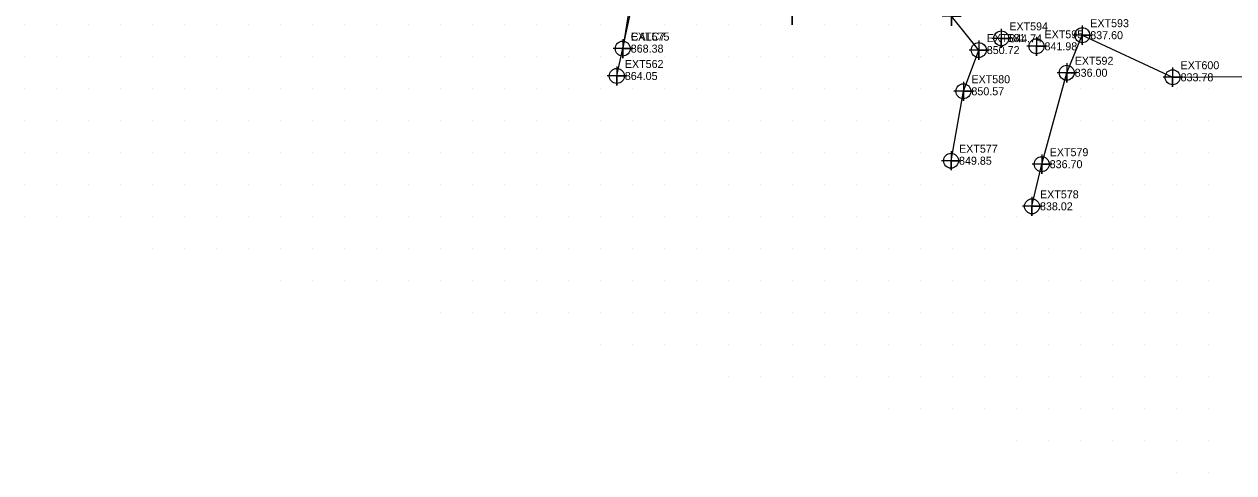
# Model space of a CAD drawing. Extents: x 1762120 to 1766775, y 709485 to 712965.
# Drawn here: x 1762430 to 1762807.8, y 712460 to 712600.2 of the extents above; entities that cross this region are included whole.
import ezdxf

# ---------------------------------------------------------------- set-up
doc = ezdxf.new("R2010")
doc.units = 0
for name, color, linetype in [('Exist Building', 7, 'Continuous'), ('Exist Building Cogo Elevation', 7, 'Continuous'), ('Exist Building Cogo Number', 7, 'Continuous'), ('Exist Building Cogo Point CELL', 7, 'Continuous'), ('Exist DTM Breakline', 7, 'Continuous'), ('Exist DTM Breakline Cogo Elevation', 7, 'Continuous'), ('Exist DTM Breakline Cogo Number', 7, 'Continuous'), ('Exist DTM Breakline Cogo Point CELL', 7, 'Continuous'), ('Exist DTM Drainline Cogo Elevation', 7, 'Continuous'), ('Exist DTM Drainline Cogo Number', 7, 'Continuous'), ('Exist DTM Drainline Cogo Point CELL', 7, 'Continuous'), ('Exist DTM QL2 LIDAR Elevation Point', 7, 'Continuous'), ('Exist DTM Regular Point CELL', 7, 'Continuous')]:
    doc.layers.add(name, color=color, linetype=linetype)

msp = doc.modelspace()

# ---------------------------------------------------------------- linework, layer by layer
at = {"layer": 'Exist Building'}
msp.add_lwpolyline([(1762599.52, 712660.55), (1762603.8, 712657.24), (1762612.48, 712646.81), (1762616.85, 712638.07), (1762621.8, 712624.37), (1762620.27, 712613.6), (1762616.96, 712592.54)], dxfattribs=at)
at = {"layer": 'Exist Building Cogo Point CELL'}
msp.add_lwpolyline([(1762616.96, 712595.54), (1762616.96, 712589.54), (1762616.96, 712592.54), (1762619.96, 712592.54), (1762613.96, 712592.54)], dxfattribs=at)
msp.add_circle((1762616.96, 712592.54), 2.34, dxfattribs=at)
at = {"layer": 'Exist DTM Breakline'}
for points in [[(1762615.11, 712583.99), (1762620.08, 712607.1), (1762622.12, 712625.39), (1762617.91, 712637.23), (1762609.81, 712651.19), (1762604.91, 712656.95), (1762600.21, 712661.1)], [(1762599.52, 712660.55), (1762603.8, 712657.24), (1762612.39, 712646.67), (1762616.85, 712638.07), (1762621.8, 712624.37), (1762620.27, 712613.6), (1762616.98, 712592.72)], [(1762719.5, 712557.51), (1762723.37, 712579.21), (1762728.17, 712592.08), (1762719.69, 712602.68), (1762720.68, 712608.52), (1762728.46, 712607.7), (1762735.49, 712603.43), (1762739.91, 712614.08), (1762743.86, 712621.24), (1762758.62, 712619.92), (1762767.95, 712615.27), (1762785.33, 712612.97), (1762818.77, 712608.04), (1762844.34, 712603.2), (1762875.47, 712595.47), (1762904.98, 712592.7), (1762941.56, 712585.95), (1762969.55, 712578.67)], [(1762744.79, 712543.26), (1762747.82, 712556.43), (1762755.63, 712584.99), (1762760.49, 712596.73), (1762788.71, 712583.59), (1762810.99, 712583.79), (1762841.1, 712578.61), (1762868.62, 712575.07), (1762897.75, 712577.65), (1762898.22, 712561.48), (1762885.56, 712560.4), (1762873.7, 712557.52), (1762863.74, 712551.2)]]:
    msp.add_lwpolyline(points, dxfattribs=at)
at = {"layer": 'Exist DTM Breakline Cogo Point CELL'}
for points in [[(1762719.69, 712605.68), (1762719.69, 712599.68), (1762719.69, 712602.68), (1762722.69, 712602.68), (1762716.69, 712602.68)], [(1762760.49, 712599.73), (1762760.49, 712593.73), (1762760.49, 712596.73), (1762763.49, 712596.73), (1762757.49, 712596.73)], [(1762616.96, 712595.54), (1762616.96, 712589.54), (1762616.96, 712592.54), (1762619.96, 712592.54), (1762613.96, 712592.54)], [(1762728.17, 712595.08), (1762728.17, 712589.08), (1762728.17, 712592.08), (1762731.17, 712592.08), (1762725.17, 712592.08)], [(1762615.11, 712586.99), (1762615.11, 712580.99), (1762615.11, 712583.99), (1762618.11, 712583.99), (1762612.11, 712583.99)], [(1762755.63, 712587.99), (1762755.63, 712581.99), (1762755.63, 712584.99), (1762758.63, 712584.99), (1762752.63, 712584.99)], [(1762788.71, 712586.59), (1762788.71, 712580.59), (1762788.71, 712583.59), (1762791.71, 712583.59), (1762785.71, 712583.59)], [(1762723.37, 712582.21), (1762723.37, 712576.21), (1762723.37, 712579.21), (1762726.37, 712579.21), (1762720.37, 712579.21)], [(1762719.5, 712560.51), (1762719.5, 712554.51), (1762719.5, 712557.51), (1762722.5, 712557.51), (1762716.5, 712557.51)], [(1762747.82, 712559.43), (1762747.82, 712553.43), (1762747.82, 712556.43), (1762750.82, 712556.43), (1762744.82, 712556.43)], [(1762744.79, 712546.26), (1762744.79, 712540.26), (1762744.79, 712543.26), (1762747.79, 712543.26), (1762741.79, 712543.26)]]:
    msp.add_lwpolyline(points, dxfattribs=at)
for centre in [(1762760.49, 712596.73), (1762616.96, 712592.54), (1762728.17, 712592.08), (1762615.11, 712583.99), (1762755.63, 712584.99), (1762788.71, 712583.59), (1762723.37, 712579.21), (1762719.5, 712557.51), (1762747.82, 712556.43), (1762744.79, 712543.26)]:
    msp.add_circle(centre, 2.34, dxfattribs=at)
at = {"layer": 'Exist DTM Drainline Cogo Point CELL'}
for points in [[(1762735.2, 712598.74), (1762735.2, 712592.74), (1762735.2, 712595.74), (1762738.2, 712595.74), (1762732.2, 712595.74)], [(1762746.2, 712596.26), (1762746.2, 712590.26), (1762746.2, 712593.26), (1762749.2, 712593.26), (1762743.2, 712593.26)]]:
    msp.add_lwpolyline(points, dxfattribs=at)
for centre in [(1762735.2, 712595.74), (1762746.2, 712593.26)]:
    msp.add_circle(centre, 2.34, dxfattribs=at)
at = {"layer": 'Exist DTM QL2 LIDAR Elevation Point'}
for p, q in [((1762430, 712600), (1762430, 712600)), ((1762440, 712600), (1762440, 712600)), ((1762450, 712600), (1762450, 712600)), ((1762460, 712600), (1762460, 712600)), ((1762470, 712600), (1762470, 712600)), ((1762480, 712600), (1762480, 712600)), ((1762490, 712600), (1762490, 712600)), ((1762500, 712600), (1762500, 712600)), ((1762510, 712600), (1762510, 712600)), ((1762520, 712600), (1762520, 712600)), ((1762530, 712600), (1762530, 712600)), ((1762540, 712600), (1762540, 712600)), ((1762550, 712600), (1762550, 712600)), ((1762560, 712600), (1762560, 712600)), ((1762570, 712600), (1762570, 712600)), ((1762580, 712600), (1762580, 712600)), ((1762590, 712600), (1762590, 712600)), ((1762600, 712600), (1762600, 712600)), ((1762610, 712600), (1762610, 712600)), ((1762630, 712600), (1762630, 712600)), ((1762640, 712600), (1762640, 712600)), ((1762650, 712600), (1762650, 712600)), ((1762660, 712600), (1762660, 712600)), ((1762670, 712600), (1762670, 712600)), ((1762680, 712600), (1762680, 712600)), ((1762690, 712600), (1762690, 712600)), ((1762700, 712600), (1762700, 712600)), ((1762710, 712600), (1762710, 712600)), ((1762430, 712590), (1762430, 712590)), ((1762440, 712590), (1762440, 712590)), ((1762450, 712590), (1762450, 712590)), ((1762460, 712590), (1762460, 712590)), ((1762470, 712590), (1762470, 712590)), ((1762480, 712590), (1762480, 712590)), ((1762490, 712590), (1762490, 712590)), ((1762500, 712590), (1762500, 712590)), ((1762510, 712590), (1762510, 712590)), ((1762520, 712590), (1762520, 712590)), ((1762530, 712590), (1762530, 712590)), ((1762540, 712590), (1762540, 712590)), ((1762550, 712590), (1762550, 712590)), ((1762560, 712590), (1762560, 712590)), ((1762570, 712590), (1762570, 712590)), ((1762580, 712590), (1762580, 712590)), ((1762590, 712590), (1762590, 712590)), ((1762600, 712590), (1762600, 712590)), ((1762610, 712590), (1762610, 712590)), ((1762620, 712590), (1762620, 712590)), ((1762630, 712590), (1762630, 712590)), ((1762640, 712590), (1762640, 712590)), ((1762650, 712590), (1762650, 712590)), ((1762660, 712590), (1762660, 712590)), ((1762670, 712590), (1762670, 712590)), ((1762680, 712590), (1762680, 712590)), ((1762690, 712590), (1762690, 712590)), ((1762700, 712590), (1762700, 712590)), ((1762710, 712590), (1762710, 712590)), ((1762720, 712590), (1762720, 712590)), ((1762760, 712590), (1762760, 712590)), ((1762770, 712590), (1762770, 712590)), ((1762430, 712580), (1762430, 712580)), ((1762440, 712580), (1762440, 712580)), ((1762450, 712580), (1762450, 712580)), ((1762460, 712580), (1762460, 712580)), ((1762470, 712580), (1762470, 712580)), ((1762480, 712580), (1762480, 712580)), ((1762490, 712580), (1762490, 712580)), ((1762500, 712580), (1762500, 712580)), ((1762510, 712580), (1762510, 712580)), ((1762520, 712580), (1762520, 712580)), ((1762530, 712580), (1762530, 712580)), ((1762540, 712580), (1762540, 712580)), ((1762550, 712580), (1762550, 712580)), ((1762560, 712580), (1762560, 712580)), ((1762570, 712580), (1762570, 712580)), ((1762580, 712580), (1762580, 712580)), ((1762590, 712580), (1762590, 712580)), ((1762600, 712580), (1762600, 712580)), ((1762610, 712580), (1762610, 712580)), ((1762620, 712580), (1762620, 712580)), ((1762630, 712580), (1762630, 712580)), ((1762640, 712580), (1762640, 712580)), ((1762650, 712580), (1762650, 712580)), ((1762660, 712580), (1762660, 712580)), ((1762670, 712580), (1762670, 712580)), ((1762680, 712580), (1762680, 712580)), ((1762690, 712580), (1762690, 712580)), ((1762700, 712580), (1762700, 712580)), ((1762710, 712580), (1762710, 712580)), ((1762720, 712580), (1762720, 712580)), ((1762760, 712580), (1762760, 712580)), ((1762770, 712580), (1762770, 712580)), ((1762780, 712580), (1762780, 712580)), ((1762790, 712580), (1762790, 712580)), ((1762800, 712580), (1762800, 712580)), ((1762430, 712570), (1762430, 712570)), ((1762440, 712570), (1762440, 712570)), ((1762450, 712570), (1762450, 712570)), ((1762460, 712570), (1762460, 712570)), ((1762470, 712570), (1762470, 712570)), ((1762480, 712570), (1762480, 712570)), ((1762490, 712570), (1762490, 712570)), ((1762500, 712570), (1762500, 712570)), ((1762510, 712570), (1762510, 712570)), ((1762520, 712570), (1762520, 712570)), ((1762530, 712570), (1762530, 712570)), ((1762540, 712570), (1762540, 712570)), ((1762550, 712570), (1762550, 712570)), ((1762560, 712570), (1762560, 712570)), ((1762570, 712570), (1762570, 712570)), ((1762580, 712570), (1762580, 712570)), ((1762590, 712570), (1762590, 712570)), ((1762600, 712570), (1762600, 712570)), ((1762610, 712570), (1762610, 712570)), ((1762620, 712570), (1762620, 712570)), ((1762630, 712570), (1762630, 712570)), ((1762640, 712570), (1762640, 712570)), ((1762650, 712570), (1762650, 712570)), ((1762660, 712570), (1762660, 712570)), ((1762670, 712570), (1762670, 712570)), ((1762680, 712570), (1762680, 712570)), ((1762690, 712570), (1762690, 712570)), ((1762700, 712570), (1762700, 712570)), ((1762710, 712570), (1762710, 712570)), ((1762760, 712570), (1762760, 712570)), ((1762770, 712570), (1762770, 712570)), ((1762780, 712570), (1762780, 712570)), ((1762790, 712570), (1762790, 712570)), ((1762800, 712570), (1762800, 712570)), ((1762430, 712560), (1762430, 712560)), ((1762440, 712560), (1762440, 712560)), ((1762450, 712560), (1762450, 712560)), ((1762460, 712560), (1762460, 712560)), ((1762470, 712560), (1762470, 712560)), ((1762480, 712560), (1762480, 712560)), ((1762490, 712560), (1762490, 712560)), ((1762500, 712560), (1762500, 712560)), ((1762510, 712560), (1762510, 712560)), ((1762520, 712560), (1762520, 712560)), ((1762530, 712560), (1762530, 712560)), ((1762540, 712560), (1762540, 712560)), ((1762550, 712560), (1762550, 712560)), ((1762560, 712560), (1762560, 712560)), ((1762570, 712560), (1762570, 712560)), ((1762580, 712560), (1762580, 712560)), ((1762590, 712560), (1762590, 712560)), ((1762600, 712560), (1762600, 712560)), ((1762610, 712560), (1762610, 712560)), ((1762620, 712560), (1762620, 712560)), ((1762630, 712560), (1762630, 712560)), ((1762640, 712560), (1762640, 712560)), ((1762650, 712560), (1762650, 712560)), ((1762660, 712560), (1762660, 712560)), ((1762670, 712560), (1762670, 712560)), ((1762680, 712560), (1762680, 712560)), ((1762690, 712560), (1762690, 712560)), ((1762700, 712560), (1762700, 712560)), ((1762710, 712560), (1762710, 712560)), ((1762760, 712560), (1762760, 712560)), ((1762770, 712560), (1762770, 712560)), ((1762780, 712560), (1762780, 712560)), ((1762790, 712560), (1762790, 712560)), ((1762800, 712560), (1762800, 712560)), ((1762430, 712550), (1762430, 712550)), ((1762440, 712550), (1762440, 712550)), ((1762450, 712550), (1762450, 712550)), ((1762460, 712550), (1762460, 712550)), ((1762470, 712550), (1762470, 712550)), ((1762480, 712550), (1762480, 712550)), ((1762490, 712550), (1762490, 712550)), ((1762500, 712550), (1762500, 712550)), ((1762510, 712550), (1762510, 712550)), ((1762520, 712550), (1762520, 712550)), ((1762530, 712550), (1762530, 712550)), ((1762540, 712550), (1762540, 712550)), ((1762550, 712550), (1762550, 712550)), ((1762560, 712550), (1762560, 712550)), ((1762570, 712550), (1762570, 712550)), ((1762580, 712550), (1762580, 712550)), ((1762590, 712550), (1762590, 712550)), ((1762600, 712550), (1762600, 712550)), ((1762610, 712550), (1762610, 712550)), ((1762620, 712550), (1762620, 712550)), ((1762630, 712550), (1762630, 712550)), ((1762640, 712550), (1762640, 712550)), ((1762650, 712550), (1762650, 712550)), ((1762660, 712550), (1762660, 712550)), ((1762670, 712550), (1762670, 712550)), ((1762680, 712550), (1762680, 712550)), ((1762690, 712550), (1762690, 712550)), ((1762700, 712550), (1762700, 712550)), ((1762710, 712550), (1762710, 712550)), ((1762720, 712550), (1762720, 712550)), ((1762730, 712550), (1762730, 712550)), ((1762750, 712550), (1762750, 712550)), ((1762760, 712550), (1762760, 712550)), ((1762770, 712550), (1762770, 712550)), ((1762780, 712550), (1762780, 712550)), ((1762790, 712550), (1762790, 712550)), ((1762800, 712550), (1762800, 712550)), ((1762430, 712540), (1762430, 712540)), ((1762440, 712540), (1762440, 712540)), ((1762450, 712540), (1762450, 712540)), ((1762460, 712540), (1762460, 712540)), ((1762470, 712540), (1762470, 712540)), ((1762480, 712540), (1762480, 712540)), ((1762490, 712540), (1762490, 712540)), ((1762500, 712540), (1762500, 712540)), ((1762510, 712540), (1762510, 712540)), ((1762520, 712540), (1762520, 712540)), ((1762530, 712540), (1762530, 712540)), ((1762540, 712540), (1762540, 712540)), ((1762550, 712540), (1762550, 712540)), ((1762560, 712540), (1762560, 712540)), ((1762570, 712540), (1762570, 712540)), ((1762580, 712540), (1762580, 712540)), ((1762590, 712540), (1762590, 712540)), ((1762600, 712540), (1762600, 712540)), ((1762610, 712540), (1762610, 712540)), ((1762620, 712540), (1762620, 712540)), ((1762630, 712540), (1762630, 712540)), ((1762640, 712540), (1762640, 712540)), ((1762650, 712540), (1762650, 712540)), ((1762660, 712540), (1762660, 712540)), ((1762670, 712540), (1762670, 712540)), ((1762680, 712540), (1762680, 712540)), ((1762690, 712540), (1762690, 712540)), ((1762700, 712540), (1762700, 712540)), ((1762710, 712540), (1762710, 712540)), ((1762720, 712540), (1762720, 712540)), ((1762730, 712540), (1762730, 712540)), ((1762740, 712540), (1762740, 712540)), ((1762750, 712540), (1762750, 712540)), ((1762760, 712540), (1762760, 712540)), ((1762770, 712540), (1762770, 712540)), ((1762780, 712540), (1762780, 712540)), ((1762790, 712540), (1762790, 712540)), ((1762800, 712540), (1762800, 712540)), ((1762470, 712530), (1762470, 712530)), ((1762480, 712530), (1762480, 712530)), ((1762490, 712530), (1762490, 712530)), ((1762500, 712530), (1762500, 712530)), ((1762510, 712530), (1762510, 712530)), ((1762520, 712530), (1762520, 712530)), ((1762530, 712530), (1762530, 712530)), ((1762540, 712530), (1762540, 712530)), ((1762550, 712530), (1762550, 712530)), ((1762560, 712530), (1762560, 712530)), ((1762570, 712530), (1762570, 712530)), ((1762580, 712530), (1762580, 712530)), ((1762590, 712530), (1762590, 712530)), ((1762600, 712530), (1762600, 712530)), ((1762610, 712530), (1762610, 712530)), ((1762620, 712530), (1762620, 712530)), ((1762630, 712530), (1762630, 712530)), ((1762640, 712530), (1762640, 712530)), ((1762650, 712530), (1762650, 712530)), ((1762660, 712530), (1762660, 712530)), ((1762670, 712530), (1762670, 712530)), ((1762680, 712530), (1762680, 712530)), ((1762690, 712530), (1762690, 712530)), ((1762700, 712530), (1762700, 712530)), ((1762710, 712530), (1762710, 712530)), ((1762720, 712530), (1762720, 712530)), ((1762730, 712530), (1762730, 712530)), ((1762740, 712530), (1762740, 712530)), ((1762750, 712530), (1762750, 712530)), ((1762760, 712530), (1762760, 712530)), ((1762770, 712530), (1762770, 712530)), ((1762780, 712530), (1762780, 712530)), ((1762790, 712530), (1762790, 712530)), ((1762800, 712530), (1762800, 712530)), ((1762510, 712520), (1762510, 712520)), ((1762520, 712520), (1762520, 712520)), ((1762530, 712520), (1762530, 712520)), ((1762540, 712520), (1762540, 712520)), ((1762550, 712520), (1762550, 712520)), ((1762560, 712520), (1762560, 712520)), ((1762570, 712520), (1762570, 712520)), ((1762580, 712520), (1762580, 712520)), ((1762590, 712520), (1762590, 712520)), ((1762600, 712520), (1762600, 712520)), ((1762610, 712520), (1762610, 712520)), ((1762620, 712520), (1762620, 712520)), ((1762630, 712520), (1762630, 712520)), ((1762640, 712520), (1762640, 712520)), ((1762650, 712520), (1762650, 712520)), ((1762660, 712520), (1762660, 712520)), ((1762670, 712520), (1762670, 712520)), ((1762680, 712520), (1762680, 712520)), ((1762690, 712520), (1762690, 712520)), ((1762700, 712520), (1762700, 712520)), ((1762710, 712520), (1762710, 712520)), ((1762720, 712520), (1762720, 712520)), ((1762730, 712520), (1762730, 712520)), ((1762740, 712520), (1762740, 712520)), ((1762750, 712520), (1762750, 712520)), ((1762760, 712520), (1762760, 712520)), ((1762770, 712520), (1762770, 712520)), ((1762780, 712520), (1762780, 712520)), ((1762790, 712520), (1762790, 712520)), ((1762800, 712520), (1762800, 712520)), ((1762560, 712510), (1762560, 712510)), ((1762570, 712510), (1762570, 712510)), ((1762580, 712510), (1762580, 712510)), ((1762590, 712510), (1762590, 712510)), ((1762600, 712510), (1762600, 712510)), ((1762610, 712510), (1762610, 712510)), ((1762620, 712510), (1762620, 712510)), ((1762630, 712510), (1762630, 712510)), ((1762640, 712510), (1762640, 712510)), ((1762650, 712510), (1762650, 712510)), ((1762660, 712510), (1762660, 712510)), ((1762670, 712510), (1762670, 712510)), ((1762680, 712510), (1762680, 712510)), ((1762690, 712510), (1762690, 712510)), ((1762700, 712510), (1762700, 712510)), ((1762710, 712510), (1762710, 712510)), ((1762720, 712510), (1762720, 712510)), ((1762730, 712510), (1762730, 712510)), ((1762740, 712510), (1762740, 712510)), ((1762750, 712510), (1762750, 712510)), ((1762760, 712510), (1762760, 712510)), ((1762770, 712510), (1762770, 712510)), ((1762780, 712510), (1762780, 712510)), ((1762790, 712510), (1762790, 712510)), ((1762800, 712510), (1762800, 712510)), ((1762610, 712500), (1762610, 712500)), ((1762620, 712500), (1762620, 712500)), ((1762630, 712500), (1762630, 712500)), ((1762640, 712500), (1762640, 712500)), ((1762650, 712500), (1762650, 712500)), ((1762660, 712500), (1762660, 712500)), ((1762670, 712500), (1762670, 712500)), ((1762680, 712500), (1762680, 712500)), ((1762690, 712500), (1762690, 712500)), ((1762700, 712500), (1762700, 712500)), ((1762710, 712500), (1762710, 712500)), ((1762720, 712500), (1762720, 712500)), ((1762730, 712500), (1762730, 712500)), ((1762740, 712500), (1762740, 712500)), ((1762750, 712500), (1762750, 712500)), ((1762760, 712500), (1762760, 712500)), ((1762770, 712500), (1762770, 712500)), ((1762780, 712500), (1762780, 712500)), ((1762790, 712500), (1762790, 712500)), ((1762800, 712500), (1762800, 712500)), ((1762650, 712490), (1762650, 712490)), ((1762660, 712490), (1762660, 712490)), ((1762670, 712490), (1762670, 712490)), ((1762680, 712490), (1762680, 712490)), ((1762690, 712490), (1762690, 712490)), ((1762700, 712490), (1762700, 712490)), ((1762710, 712490), (1762710, 712490)), ((1762720, 712490), (1762720, 712490)), ((1762730, 712490), (1762730, 712490)), ((1762740, 712490), (1762740, 712490)), ((1762750, 712490), (1762750, 712490)), ((1762760, 712490), (1762760, 712490)), ((1762770, 712490), (1762770, 712490)), ((1762780, 712490), (1762780, 712490)), ((1762790, 712490), (1762790, 712490)), ((1762800, 712490), (1762800, 712490)), ((1762700, 712480), (1762700, 712480)), ((1762710, 712480), (1762710, 712480)), ((1762720, 712480), (1762720, 712480)), ((1762730, 712480), (1762730, 712480)), ((1762740, 712480), (1762740, 712480)), ((1762750, 712480), (1762750, 712480)), ((1762760, 712480), (1762760, 712480)), ((1762770, 712480), (1762770, 712480)), ((1762780, 712480), (1762780, 712480)), ((1762790, 712480), (1762790, 712480)), ((1762800, 712480), (1762800, 712480)), ((1762740, 712470), (1762740, 712470)), ((1762750, 712470), (1762750, 712470)), ((1762760, 712470), (1762760, 712470)), ((1762770, 712470), (1762770, 712470)), ((1762780, 712470), (1762780, 712470)), ((1762790, 712470), (1762790, 712470)), ((1762800, 712470), (1762800, 712470)), ((1762790, 712460), (1762790, 712460)), ((1762800, 712460), (1762800, 712460))]:
    msp.add_line(p, q, dxfattribs=at)
at = {"layer": 'Exist DTM Regular Point CELL'}
msp.add_lwpolyline([(1762669.89, 712605.99), (1762669.89, 712599.99), (1762669.89, 712602.99), (1762672.89, 712602.99), (1762666.89, 712602.99)], dxfattribs=at)

# ---------------------------------------------------------------- texts
at = {"layer": 'Exist Building Cogo Elevation'}
msp.add_text('868.38', height=2.5, dxfattribs=at).set_placement((1762619.46, 712591.29))
at = {"layer": 'Exist Building Cogo Number'}
msp.add_text('CALC7', height=2.5, dxfattribs=at).set_placement((1762619.46, 712595.04))
at = {"layer": 'Exist DTM Breakline Cogo Elevation'}
for s, p in [('837.60', (1762762.99, 712595.48)), ('868.38', (1762619.46, 712591.29)), ('850.72', (1762730.67, 712590.83)), ('864.05', (1762617.61, 712582.74)), ('836.00', (1762758.13, 712583.74)), ('833.78', (1762791.21, 712582.34)), ('850.57', (1762725.87, 712577.96)), ('849.85', (1762722, 712556.26)), ('836.70', (1762750.32, 712555.18)), ('838.02', (1762747.29, 712542.01))]:
    msp.add_text(s, height=2.5, dxfattribs=at).set_placement(p)
at = {"layer": 'Exist DTM Breakline Cogo Number'}
for s, p in [('EXT593', (1762762.99, 712599.23)), ('EXT575', (1762619.46, 712595.04)), ('EXT581', (1762730.67, 712594.58)), ('EXT562', (1762617.61, 712586.49)), ('EXT592', (1762758.13, 712587.49)), ('EXT600', (1762791.21, 712586.09)), ('EXT580', (1762725.87, 712581.71)), ('EXT577', (1762722, 712560.01)), ('EXT579', (1762750.32, 712558.93)), ('EXT578', (1762747.29, 712545.76))]:
    msp.add_text(s, height=2.5, dxfattribs=at).set_placement(p)
at = {"layer": 'Exist DTM Drainline Cogo Elevation'}
for s, p in [('844.74', (1762737.7, 712594.49)), ('841.98', (1762748.7, 712592.01))]:
    msp.add_text(s, height=2.5, dxfattribs=at).set_placement(p)
at = {"layer": 'Exist DTM Drainline Cogo Number'}
for s, p in [('EXT594', (1762737.7, 712598.24)), ('EXT595', (1762748.7, 712595.76))]:
    msp.add_text(s, height=2.5, dxfattribs=at).set_placement(p)

doc.saveas('drawing.dxf')
